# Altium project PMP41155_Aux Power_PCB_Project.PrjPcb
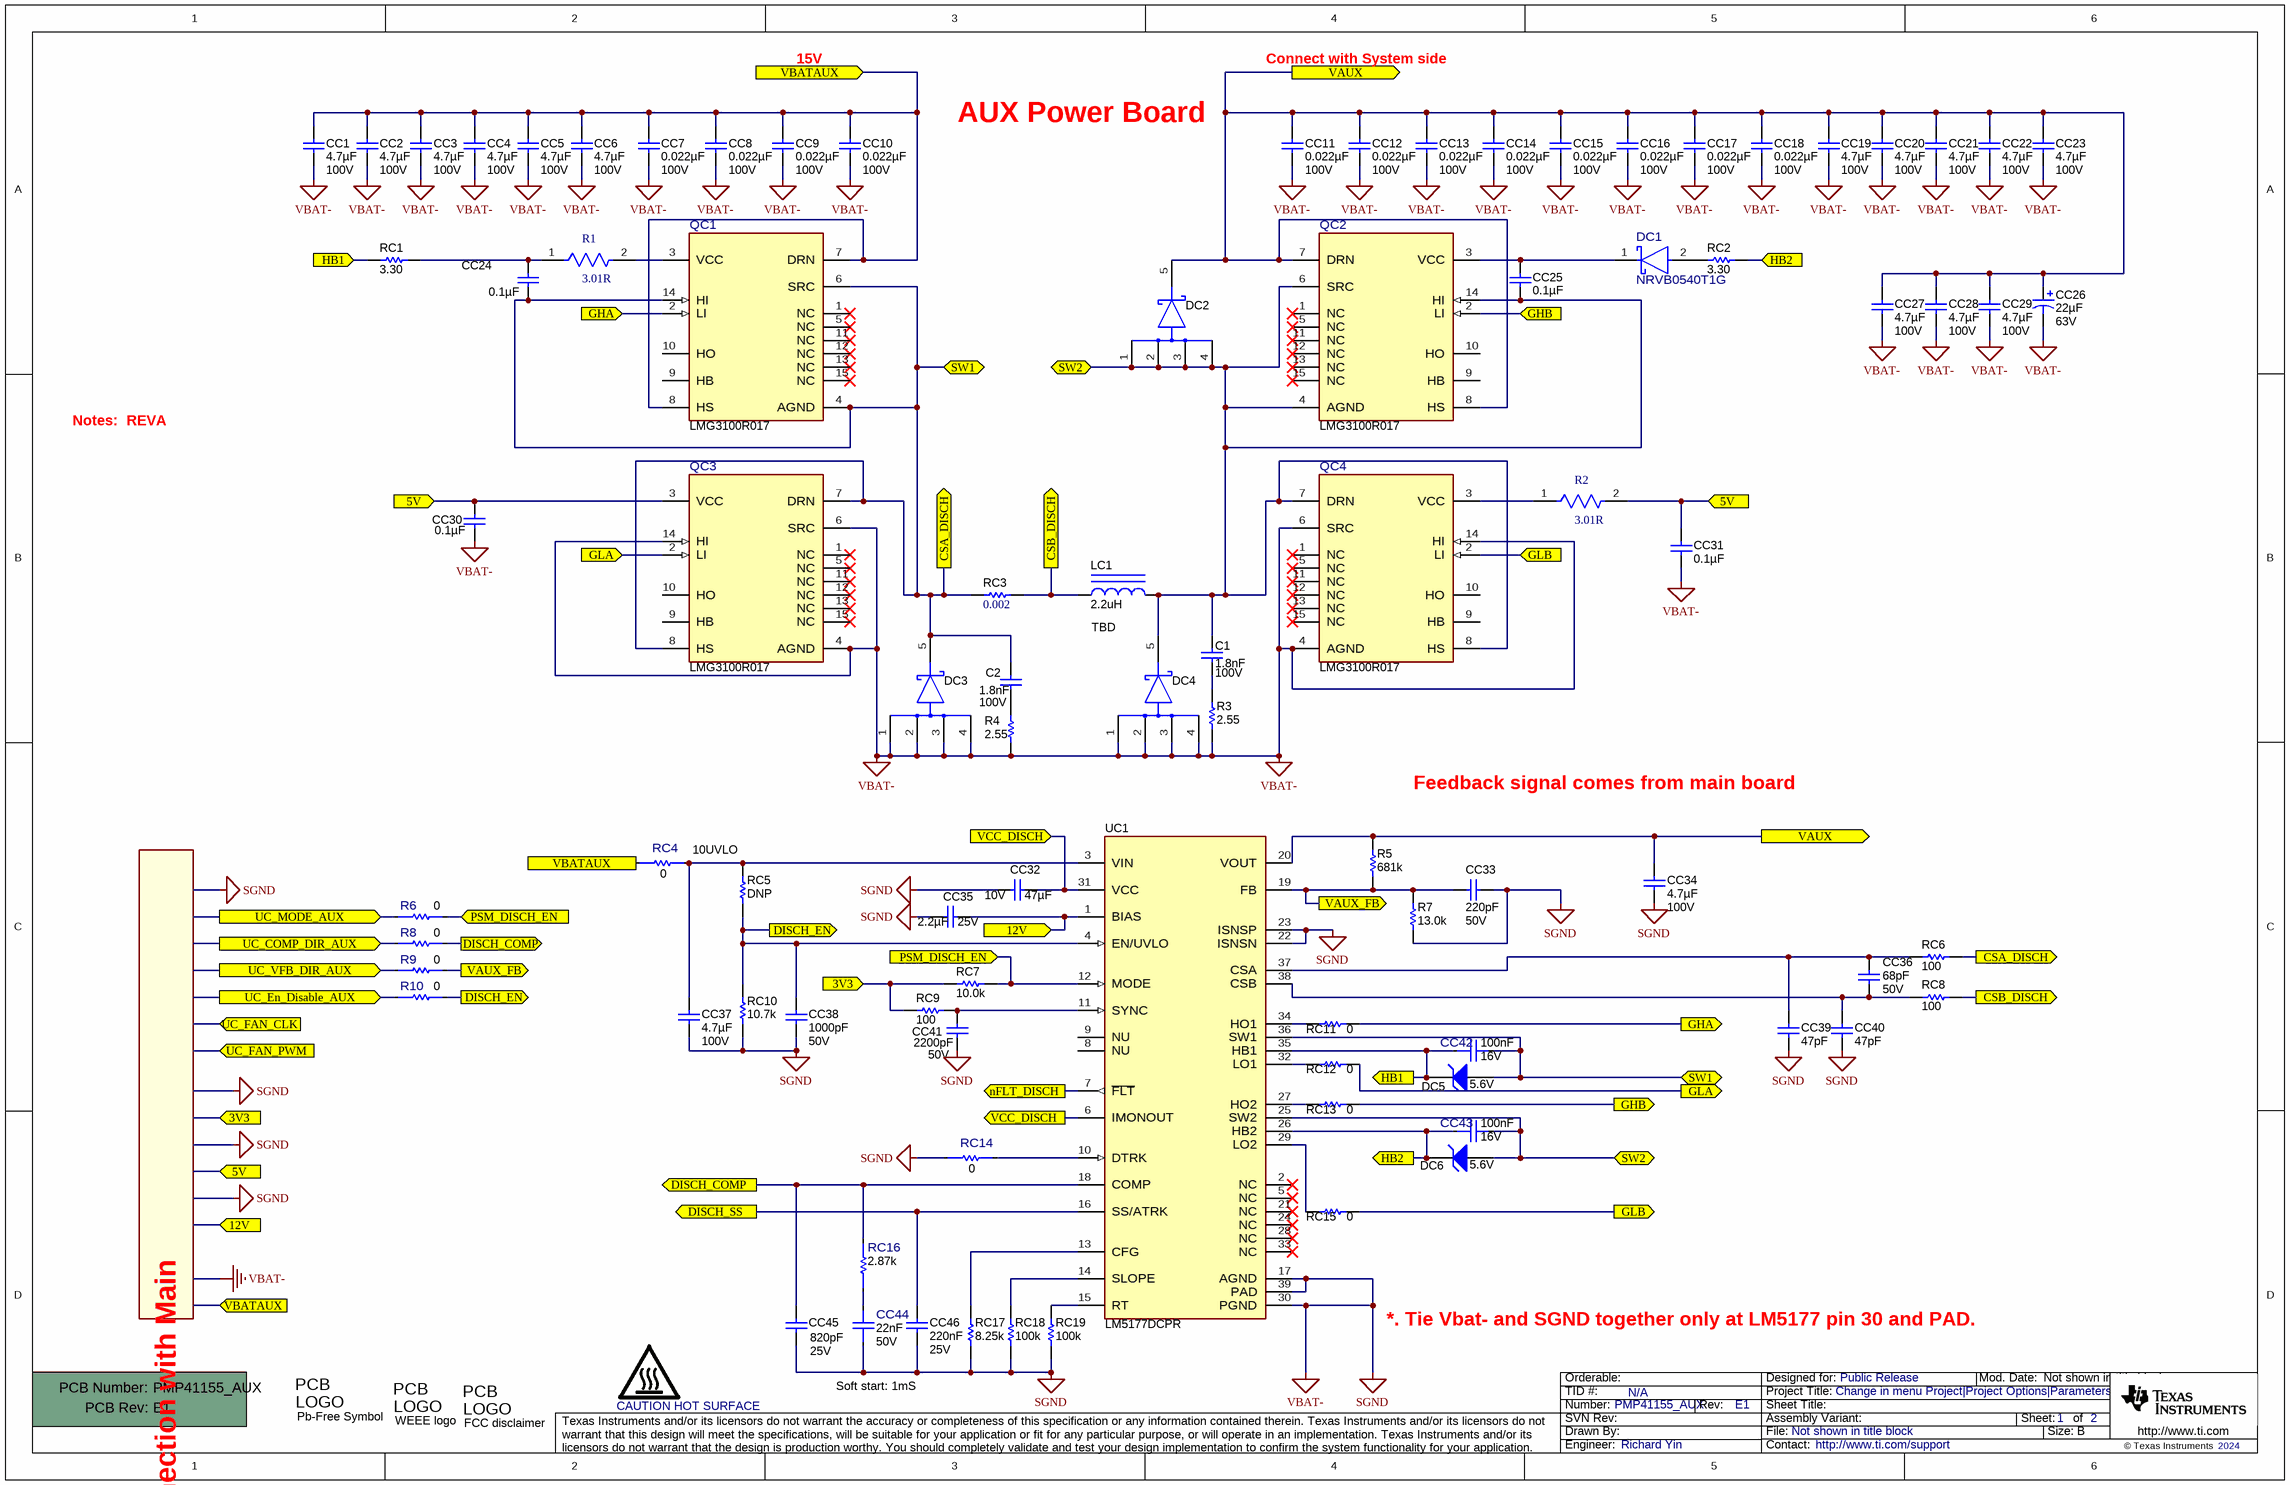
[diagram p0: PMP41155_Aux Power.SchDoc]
CopyrightYear: 2024; PCB_Layout: Richard Yin; PCB_Rev: E1; PRJ_Customer: Public Release; PRJ_Engineer: Richard Yin; PRJ_Number: PMP41155_AUX; PRJ_Title: Change in menu Project|Project Options|Parameters; SCH_Rev: E1; TechSupport: http://www.ti.com/support; TID: N/A
2 sheets, 131 parts. Net scope: flat (ports and power ports of the same name join across sheets).
Board file: PMP41155_Aux Power.PcbDoc
Sheets:
  PMP41155_Aux Power.SchDoc
  PMP41155_Aux Power_D2D.SchDoc

## Sheet PMP41155_Aux Power.SchDoc
size 431 x 279 mm; Date: Not shown in title block; ApprovedBy: Not shown in title block; CheckedBy: Not shown in title block; Author: Not shown in title block; CompanyName: Not shown in title block; Engineer: Not shown in title block; Organization: Not shown in title block; Address1: Not shown in title block; Address2: Not shown in title block; Address3: Not shown in title block; Address4: Not shown in title block; DocumentNumber: 1; Revision: Use project parameter SCH_Rev; SheetNumber: 1; SheetTotal: 2; PageSetup: Record=PageOptions¦CenterHorizontal=True¦CenterVertical=True¦PrintScale=1.00¦XCorrection=1.00¦YCorrection=1.00¦PrintKind=0¦BorderSize=5000000¦LeftOffset=0¦BottomOffset=0¦Orientation=2¦PaperLength=1000¦PaperWidth=1000¦Scale=100¦PaperSource=15¦PrintQuality=600¦MediaType=1¦DitherType=10¦PaperKind=Letter¦PrintScaleMode=1

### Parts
!PCB1  Printed Circuit Board  (value not drawn)  (mechanical)
C1  Cap_F: 1.8nF  VDC_V: 100V  [0603]  (hidden comment: GRM188R72A182KA01D)
C2  Cap_F: 1.8nF  VDC_V: 100V  [0603]  (hidden comment: GRM188R72A182KA01D)
CC1  ValueDisplayed: 4.7µF  Value2: 100V  [1206_180]  (hidden comment: GRJ31CC72A475KE01L)
CC2  ValueDisplayed: 4.7µF  Value2: 100V  [1206_180]  (hidden comment: GRJ31CC72A475KE01L)
CC3  ValueDisplayed: 4.7µF  Value2: 100V  [1206_180]  (hidden comment: GRJ31CC72A475KE01L)
CC4  ValueDisplayed: 4.7µF  Value2: 100V  [1206_180]  (hidden comment: GRJ31CC72A475KE01L)
CC5  ValueDisplayed: 4.7µF  Value2: 100V  [1206_180]  (hidden comment: GRJ31CC72A475KE01L)
CC6  ValueDisplayed: 4.7µF  Value2: 100V  [1206_180]  (hidden comment: GRJ31CC72A475KE01L)
CC7  ValueDisplayed: 0.022µF  Value2: 100V  [0603]  (hidden comment: CGA3E2X7R2A223K080AA)
CC8  ValueDisplayed: 0.022µF  Value2: 100V  [0603]  (hidden comment: CGA3E2X7R2A223K080AA)
CC9  ValueDisplayed: 0.022µF  Value2: 100V  [0603]  (hidden comment: CGA3E2X7R2A223K080AA)
CC10  ValueDisplayed: 0.022µF  Value2: 100V  [0603]  (hidden comment: CGA3E2X7R2A223K080AA)
CC11  ValueDisplayed: 0.022µF  Value2: 100V  [0603]  (hidden comment: CGA3E2X7R2A223K080AA)
CC12  ValueDisplayed: 0.022µF  Value2: 100V  [0603]  (hidden comment: CGA3E2X7R2A223K080AA)
CC13  ValueDisplayed: 0.022µF  Value2: 100V  [0603]  (hidden comment: CGA3E2X7R2A223K080AA)
CC14  ValueDisplayed: 0.022µF  Value2: 100V  [0603]  (hidden comment: CGA3E2X7R2A223K080AA)
CC15  ValueDisplayed: 0.022µF  Value2: 100V  [0603]  (hidden comment: CGA3E2X7R2A223K080AA)
CC16  ValueDisplayed: 0.022µF  Value2: 100V  [0603]  (hidden comment: CGA3E2X7R2A223K080AA)
CC17  ValueDisplayed: 0.022µF  Value2: 100V  [0603]  (hidden comment: CGA3E2X7R2A223K080AA)
CC18  ValueDisplayed: 0.022µF  Value2: 100V  [0603]  (hidden comment: CGA3E2X7R2A223K080AA)
CC19  ValueDisplayed: 4.7µF  Value2: 100V  [1206_180]  (hidden comment: GRJ31CC72A475KE01L)
CC20  ValueDisplayed: 4.7µF  Value2: 100V  [1206_180]  (hidden comment: GRJ31CC72A475KE01L)
CC21  ValueDisplayed: 4.7µF  Value2: 100V  [1206_180]  (hidden comment: GRJ31CC72A475KE01L)
CC22  ValueDisplayed: 4.7µF  Value2: 100V  [1206_180]  (hidden comment: GRJ31CC72A475KE01L)
CC23  ValueDisplayed: 4.7µF  Value2: 100V  [1206_180]  (hidden comment: GRJ31CC72A475KE01L)
CC24  ValueDisplayed: 0.1µF  [0402]  (hidden comment: C0402C104K4RACAUTO)
CC25  ValueDisplayed: 0.1µF  [0402]  (hidden comment: C0402C104K4RACAUTO)
CC26  ValueDisplayed: 22µF  Value2: 63V  [SM_RADIAL_D]  (hidden comment: 63PFV22M6.3X8)
CC27  ValueDisplayed: 4.7µF  Value2: 100V  [1206_180]  (hidden comment: GRJ31CC72A475KE01L)
CC28  ValueDisplayed: 4.7µF  Value2: 100V  [1206_180]  (hidden comment: GRJ31CC72A475KE01L)
CC29  ValueDisplayed: 4.7µF  Value2: 100V  [1206_180]  (hidden comment: GRJ31CC72A475KE01L)
CC30  ValueDisplayed: 0.1µF  [0402]  (hidden comment: C0402C104K4RACAUTO)
CC31  ValueDisplayed: 0.1µF  [0402]  (hidden comment: C0402C104K4RACAUTO)
CC32  VDC_V: 10V  ValueDisplayed: 47µF  [0805_HV]  (hidden comment: GRM21BR61A476ME15L)
CC33  ValueDisplayed: 220pF  Value2: 50V  [0603]  (hidden comment: GRM188R71H221KA01D)
CC34  ValueDisplayed: 4.7µF  Value2: 100V  [1206_180]  (hidden comment: GRJ31CC72A475KE01L)
CC35  ValueDisplayed: 2.2µF  Value2: 25V  [0805_HV]  (hidden comment: GRM219R61E225KA12D)
CC36  ValueDisplayed: 68pF  Value2: 50V  [0603]  (hidden comment: 06035A680JAT2A)
CC37  ValueDisplayed: 4.7µF  Value2: 100V  [1206_180]  (hidden comment: GRJ31CC72A475KE01L)
CC38  ValueDisplayed: 1000pF  Value2: 50V  [0603]  (hidden comment: GRM1885C1H102JA01D)
CC39  ValueDisplayed: 47pF  [0402]  (hidden comment: GRM1555C1H470FA01D)
CC40  ValueDisplayed: 47pF  [0402]  (hidden comment: GRM1555C1H470FA01D)
CC41  ValueDisplayed: 2200pF  Value2: 50V  [0603]  (hidden comment: GRM188R61H222KA01D)
CC42  Cap_F: 100nF  VDC_V: 16V  [FP-0603YC104JAT2A_0603-MFG]  (hidden comment: 0603YC104JAT2A)
CC43  Cap_F: 100nF  VDC_V: 16V  [FP-0603YC104JAT2A_0603-MFG]  (hidden comment: 0603YC104JAT2A)
CC44  Cap_F: 22nF  VDC_V: 50V  [FP-CL10B223KB8NNNC_0603-IPC_C]  (hidden comment: CL10B223KB8NNNC)
CC45  VDC_V: 25V  ValueDisplayed: 820pF  [0603]  (hidden comment: GRM1885C1E821JA01D)
CC46  Cap_F: 220nF  VDC_V: 25V  [0805_HV]  (hidden comment: 08053C224MAT2A)
DC1  NRVB0540T1G  [FP-NRVB0540T1G_SOD-123-MFG]
DC2  STPS30M100DJF-TR  [FP-STPS30M100DJF-TR_PowerFlat6-MFG]  (value not drawn)
DC3  STPS30M100DJF-TR  [FP-STPS30M100DJF-TR_PowerFlat6-MFG]  (value not drawn)
DC4  STPS30M100DJF-TR  [FP-STPS30M100DJF-TR_PowerFlat6-MFG]  (value not drawn)
DC5  value 5.6V  [SOD-123]  (hidden comment: MMSZ4690-E3-08)
DC6  value 5.6V  [SOD-123]  (hidden comment: MMSZ4690-E3-08)
LC1  TBD  ValueDisplayed: 2.2uH  [WE-HCB_1890]
LOGO1  CAUTION HOT SURFACE  [IEC_HotSurface_Small]  (no BOM)
Logo2  Pb-Free Symbol  [Pb-Free_Overlay_Medium]  (no BOM)
Logo3  WEEE logo  [WEEE_Minimum]  (no BOM)
Logo4  FCC disclaimer  [FCC_disclaimer]  (no BOM)
QC1  LMG3100R017  [VBE0015A-MFG]
QC2  LMG3100R017  [VBE0015A-MFG]
QC3  LMG3100R017  [VBE0015A-MFG]
QC4  LMG3100R017  [VBE0015A-MFG]
R1  Resistance: 3.01R  [FP-CRCW0402-e3-MFG]  (hidden comment: CRCW04023R01FNED)
R2  Resistance: 3.01R  [FP-CRCW0402-e3-MFG]  (hidden comment: CRCW04023R01FNED)
R3  ValueDisplayed: 2.55  [1206]  (hidden comment: CRCW12062R55FKEA)
R4  ValueDisplayed: 2.55  [1206]  (hidden comment: CRCW12062R55FKEA)
R5  ValueDisplayed: 681k  [0603]  (hidden comment: CRCW0603681KFKEA)
R6  Res_ohm: 0  [FP-D1LPC0402CJUMPF-T10_0402-MFG]  (hidden comment: D1LPC0402CJUMPF-T10)
R7  ValueDisplayed: 13.0k  [0603]  (hidden comment: CRCW060313K0FKEA)
R8  Res_ohm: 0  [FP-D1LPC0402CJUMPF-T10_0402-MFG]  (hidden comment: D1LPC0402CJUMPF-T10)
R9  Res_ohm: 0  [FP-D1LPC0402CJUMPF-T10_0402-MFG]  (hidden comment: D1LPC0402CJUMPF-T10)
R10  Res_ohm: 0  [FP-D1LPC0402CJUMPF-T10_0402-MFG]  (hidden comment: D1LPC0402CJUMPF-T10)
RC1  ValueDisplayed: 3.30  [1206]  (hidden comment: RC1206FR-073R3L)
RC2  ValueDisplayed: 3.30  [1206]  (hidden comment: RC1206FR-073R3L)
RC3  ValueDisplayed: 0.002  [0508]  (hidden comment: KRL2012E-M-R002-G-T5)
RC4  Res_ohm: 0  [FP-JR0805X35E_0805-MFG]  (hidden comment: JR0805X35E)
RC5  ValueDisplayed: DNP  [0402]  (hidden comment: CRCW040271K5FKED)
RC6  ValueDisplayed: 100  [0603]  (hidden comment: RC0603FR-07100RL)
RC7  ValueDisplayed: 10.0k  [0603]  (hidden comment: CRCW060310K0FKEA)
RC8  ValueDisplayed: 100  [0603]  (hidden comment: RC0603FR-07100RL)
RC9  ValueDisplayed: 100  [0603]  (hidden comment: CRCW0603100RFKEA)
RC10  ValueDisplayed: 10.7k  [0603]  (hidden comment: CRCW060310K7FKEA)
RC11  ValueDisplayed: 0  [0603]  (hidden comment: CRCW06030000Z0EA)
RC12  ValueDisplayed: 0  [0603]  (hidden comment: CRCW06030000Z0EA)
RC13  ValueDisplayed: 0  [0603]  (hidden comment: CRCW06030000Z0EA)
RC14  Res_ohm: 0  [FP-JR0805X35E_0805-MFG]  (hidden comment: JR0805X35E)
RC15  ValueDisplayed: 0  [0603]  (hidden comment: CRCW06030000Z0EA)
RC16  Res_ohm: 2.87k  [FP-RK73H1ETTP2871F_0402-MFG]  (hidden comment: RK73H1ETTP2871F)
RC17  ValueDisplayed: 8.25k  [0603]  (hidden comment: CRCW06038K25FKEA)
RC18  ValueDisplayed: 100k  [0603]  (hidden comment: CRCW0603100KFKEA)
RC19  ValueDisplayed: 100k  [0603]  (hidden comment: CRCW0603100KFKEA)
UC1  LM5177DCPR  [DCP0038A-MFG]

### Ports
3V3 (in), 5V (in), 12V (in), CSA_DISCH (out), CSB_DISCH (out), DISCH_COMP (out), DISCH_EN (out), DISCH_SS (out), GHA (in), GHA (out), GHB (in), GHB (out), GLA (in), GLA (out), GLB (in), GLB (out), HB1 (in), HB1 (out), HB2 (in), HB2 (out), nFLT_DISCH (out), PSM_DISCH_EN (in), SW1 (bidir), SW2 (bidir), UC_COMP_DIR_AUX (out), UC_En_Disable_AUX (out), UC_FAN_CLK (in), UC_FAN_PWM (in), UC_MODE_AUX (out), UC_VFB_DIR_AUX (out), VAUX (out), VAUX_FB (out), VBATAUX (in), VCC_DISCH (in), VCC_DISCH (out)

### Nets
12V: CC35.2 UC1.1(BIAS) ; port 12V
SGND: CC1.2 CC2.2 CC3.2 CC4.2 CC5.2 CC6.2 CC7.2 CC8.2 CC9.2 CC10.2 CC11.2 CC12.2 CC13.2 CC14.2 CC15.2 CC16.2 CC17.2 CC18.2 CC19.2 CC20.2 CC21.2 CC22.2 CC23.2 CC26.2(-) CC27.2 CC28.2 CC29.2 CC30.2 CC31.2 CC32.2 CC33.2 CC34.2 CC35.1 CC37.2 CC38.2 CC39.2 CC40.2 CC41.1 CC44.1 CC45.2 CC46.2 DC3.1(A) DC3.2(A) DC3.3(A) DC3.4(A) DC4.1(A) DC4.2(A) DC4.3(A) DC4.4(A) QC3.4(AGND) QC3.6(SRC) QC3.14(HI) QC4.4(AGND) QC4.6(SRC) QC4.14(HI) R3.1 R4.1 R7.1 RC10.1 RC14.1 RC17.1 RC18.1 RC19.1 UC1.17(AGND) UC1.22(ISNSN) UC1.23(ISNSP) UC1.30(PGND) UC1.39(PAD)  [also labelled VBAT-]
VAUX: CC11.1 CC12.1 CC13.1 CC14.1 CC15.1 CC16.1 CC17.1 CC18.1 CC19.1 CC20.1 CC21.1 CC22.1 CC23.1 CC26.1(+) CC27.1 CC28.1 CC29.1 CC34.1 DC2.5(K) QC2.7(DRN) QC2.8(HS) R5.2 UC1.20(VOUT) ; port VAUX
3V3: RC7.1 RC9.1 ; port 3V3
5V: CC30.1 CC31.1 QC3.3(VCC) R2.2 ; port 5V
CSA_DISCH: C2.1 CC24.2 CC42.2 DC3.5(K) DC5.2(A) QC1.4(AGND) QC1.6(SRC) QC1.14(HI) QC3.7(DRN) QC3.8(HS) RC3.1 RC6.2 UC1.36(SW1) ; port CSA_DISCH, port SW1
CSB_DISCH: LC1.1 RC3.2 RC8.2 ; port CSB_DISCH
DISCH_COMP: CC45.1 R8.2 RC16.2 UC1.18(COMP) ; port DISCH_COMP
DISCH_EN: CC38.1 R10.2 RC5.1 RC10.2 UC1.4(EN/UVLO) ; port DISCH_EN
DISCH_SS: CC46.1 UC1.16(SS/ATRK) ; port DISCH_SS
GHA: QC1.2(LI) RC11.2 ; port GHA
GHB: QC2.2(LI) RC13.2 ; port GHB
GLA: QC3.2(LI) RC12.2 ; port GLA
GLB: QC4.2(LI) RC15.2 ; port GLB
HB1: CC42.1 DC5.1(K) RC1.1 UC1.35(HB1) ; port HB1
HB2: CC43.1 DC6.1(K) RC2.2 UC1.26(HB2) ; port HB2
nFLT_DISCH: UC1.7(~{FLT}) ; port nFLT_DISCH
PSM_DISCH_EN: R6.2 RC7.2 UC1.12(MODE) ; port PSM_DISCH_EN
SW2: C1.1 CC25.2 CC43.2 DC2.1(A) DC2.2(A) DC2.3(A) DC2.4(A) DC4.5(K) DC6.2(A) LC1.2 QC2.4(AGND) QC2.6(SRC) QC2.14(HI) QC4.7(DRN) QC4.8(HS) UC1.25(SW2) ; port SW2
UC_COMP_DIR_AUX: R8.1 ; port UC_COMP_DIR_AUX
UC_En_Disable_AUX: R10.1 ; port UC_En_Disable_AUX
UC_MODE_AUX: R6.1 ; port UC_MODE_AUX
UC_VFB_DIR_AUX: R9.1 ; port UC_VFB_DIR_AUX
VAUX_FB: CC33.1 R5.1 R7.2 R9.2 UC1.19(FB) ; port VAUX_FB
VBATAUX: CC1.1 CC2.1 CC3.1 CC4.1 CC5.1 CC6.1 CC7.1 CC8.1 CC9.1 CC10.1 QC1.7(DRN) QC1.8(HS) RC4.1 ; port VBATAUX
VCC_DISCH: CC32.1 UC1.6(IMONOUT) UC1.31(VCC) ; port VCC_DISCH
NetC1_2: C1.2 R3.2
NetC2_2: C2.2 R4.2
NetCC24_1: CC24.1 R1.1 RC1.2
NetCC25_1: CC25.1 DC1.1(CATHODE) QC2.3(VCC)
NetCC36_1: CC36.1 CC39.1 RC6.1 UC1.37(CSA)
NetCC36_2: CC36.2 CC40.1 RC8.1 UC1.38(CSB)
NetCC37_1: CC37.1 RC4.2 RC5.2 UC1.3(VIN)
NetCC41_2: CC41.2 RC9.2 UC1.11(SYNC)
NetCC44_2: CC44.2 RC16.1
NetDC1_2: DC1.2(ANODE) RC2.1
NetQC1_3: QC1.3(VCC) R1.2
NetQC4_3: QC4.3(VCC) R2.1
NetRC11_1: RC11.1 UC1.34(HO1)
NetRC12_1: RC12.1 UC1.32(LO1)
NetRC13_1: RC13.1 UC1.27(HO2)
NetRC14_2: RC14.2 UC1.10(DTRK)
NetRC15_1: RC15.1 UC1.29(LO2)
NetRC17_2: RC17.2 UC1.13(CFG)
NetRC18_2: RC18.2 UC1.14(SLOPE)
NetRC19_2: RC19.2 UC1.15(RT)

Not connected (* = marked no-connect by the designer): QC1 1(NC)* 5(NC)* 9(HB) 10(HO) 11(NC)* 12(NC)* 13(NC)* 15(NC)*; QC2 1(NC)* 5(NC)* 9(HB) 10(HO) 11(NC)* 12(NC)* 13(NC)* 15(NC)*; QC3 1(NC)* 5(NC)* 9(HB) 10(HO) 11(NC)* 12(NC)* 13(NC)* 15(NC)*; QC4 1(NC)* 5(NC)* 9(HB) 10(HO) 11(NC)* 12(NC)* 13(NC)* 15(NC)*; UC1 2(NC)* 5(NC)* 8(NU) 9(NU) 21(NC)* 24(NC)* 28(NC)* 33(NC)*

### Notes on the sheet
- 15V
- Connect with System side
- AUX Power Board
- Notes:
- REVA
- Feedback signal comes from main board
- 10UVLO
- Connection with Main
- *. Tie Vbat- and SGND together only at LM5177 pin 30 and PAD.
- Soft start: 1mS

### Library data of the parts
!PCB1 = CMP-0003618-2: Manufacturer: Any; PartNumber: PMP41155_AUX
C1 C2 = CMP-0007473-4: CAP, CERM, 1800 pF, 100 V, +/- 10%, X7R, 0603; Manufacturer: MuRata; TaMin_C: -55°C; Polarized: N; SizeAreaWB_mm2: 4.68; Value1: Unknown; U/M: EA; Value: 1800pF; TaMax_C: 125°C; SizeZ_mm: 1; SizeX_mm: 1.6; SizeY_mm: 0.8; SizeArea_mm2: 1.28; AEC Category: Q200
CC1-CC6 CC19-CC23 CC27-CC29 CC34 CC37 = C3216X6S1H475K160AB: CAP CER 4.7UF 100V X7S 1206; Polarized: N; CompType: Capacitor; U/M: EA; Cap_F: 0.0000047; Tolerance_%: 10; VDC_V: 100; TaMin_C: -55; TaMax_C: 105; Cap_Case: 1206; SizeArea_mm2: 5.12; SizeAreaWB_mm2: 10.92; SizeX_mm: 3.2; SizeY_mm: 1.6; SizeZ_mm: 1.8; AEC Category: Q200
CC7-CC18 = CGA3E2X7R2A223K080AA: CAP, CERM, 0.022 µF, 100 V,+/- 10%, X7R, AEC-Q200 Grade 1, 0603; Manufacturer: TDK; Polarized: N; CompType: Capacitor; Value: 0.022uF; U/M: EA; Cap_F: 0.000000022; Tolerance_%: 10; ESR_ohm: 0.083542; Value1: 0.083542 ohm; VDC_V: 100; IRMS_A: 0.609312; TaMin_C: -55; TaMax_C: 125; SizeArea_mm2: 1.28; SizeAreaWB_mm2: 4.68; SizeX_mm: 1.6; SizeY_mm: 0.8; SizeZ_mm: 1; AEC Category: Q200; AEC Qualified: Y
CC24 CC25 CC30 CC31 = C0402C104K4RACAUTO: CAP, CERM, 0.1 µF, 16 V,+/- 10%, X7R, AEC-Q200 Grade 1, 0402; Manufacturer: Kemet; Polarized: N; CompType: Capacitor; Value: 0.1uF; U/M: EA; Cap_F: 0.0000001; Tolerance_%: 10; VDC_V: 16; Value2: 16V; TaMin_C: -55; TaMax_C: 125; SizeArea_mm2: 0.5; SizeAreaWB_mm2: 3; SizeX_mm: 1; SizeZ_mm: 0.6; AEC Category: Q200; AEC Qualified: Y; Green_Lifecycle: Active; Green_REACh: Passed
CC26 = EEE-FK1H220P: CAP ALUM POLY HYB 22UF 63V SMD; Manufacturer: Rubycon; Polarized: Y; CompType: Capacitor; Cap_F: 0.000022; Tolerance_%: 20; Value1: 0.88 ohm; VDC_V: 63; Cap_Case: D; SizeAreaWB_mm2: 84.28; SizeArea_mm2: 51.48; SizeX_mm: 7.8; SizeY_mm: 6.6; SizeZ_mm: 5.4; Green_Lifecycle: Active; Green_REACh: Passed
CC32 = CMP-0078699-1: CAP, CERM, 47 µF, 10 V,+/- 20%, X5R, 0805; Manufacturer: MuRata; TaMin_C: -55°C; Polarized: N; Green_Lifecycle: Active; SizeAreaWB_mm2: 6.75; Green_REACh: Passed; U/M: EA; Value: 47uF; TaMax_C: 85°C; SizeZ_mm: 1.45; SizeX_mm: 2; SizeY_mm: 1.25; Cap_Case: 0805; SizeArea_mm2: 2.5; AEC Category: Q200
CC33 = GRM188R71H221KA01D: CAP, CERM, 220 pF, 50 V,+/- 10%, X7R, 0603; Manufacturer: MuRata; Polarized: N; CompType: Capacitor; Value: 220pF; U/M: EA; Cap_F: 0.00000000022; Tolerance_%: 10; VDC_V: 50; TaMin_C: -55; TaMax_C: 125; SizeArea_mm2: 1.28; SizeAreaWB_mm2: 4.68; SizeX_mm: 1.6; SizeY_mm: 0.8; SizeZ_mm: 1; AEC Category: Q200; Green_Lifecycle: Active; Green_REACh: Passed
CC35 = GRM219R61E225KA12D: CAP, CERM, 2.2 µF, 25 V,+/- 10%, X5R, 0805; Manufacturer: MuRata; Polarized: N; CompType: Capacitor; Value: 2.2uF; U/M: EA; Cap_F: 0.0000022; Tolerance_%: 10; ESR_ohm: 0.006; Value1: 0.006 ohm; VDC_V: 25; TaMin_C: -55; TaMax_C: 85; Cap_Case: 0805; SizeArea_mm2: 2.5; SizeAreaWB_mm2: 6.75; SizeX_mm: 2; SizeY_mm: 1.25; SizeZ_mm: 1.45; AEC Category: Q200; Green_Lifecycle: Active; Green_REACh: Passed
CC36 = 06035A680JAT2A: CAP, CERM, 68 pF, 50 V,+/- 5%, C0G/NP0, 0603; Manufacturer: AVX; Polarized: N; CompType: Capacitor; Value: 68pF; U/M: EA; Cap_F: 0.000000000068; Tolerance_%: 5; ESR_ohm: 0.144; Value1: 0.144 ohm; VDC_V: 50; TaMin_C: -55; TaMax_C: 125; SizeArea_mm2: 1.28; SizeAreaWB_mm2: 4.68; SizeX_mm: 1.6; SizeY_mm: 0.8; SizeZ_mm: 1; AEC Category: Q200; Green_Lifecycle: Active; Green_REACh: Passed
CC38 = GRM1885C1H102JA01D: CAP, CERM, 1000 pF, 50 V,+/- 5%, C0G/NP0, 0603; Manufacturer: MuRata; Polarized: N; CompType: Capacitor; Value: 1000pF; U/M: EA; Cap_F: 0.000000001; Tolerance_%: 5; VDC_V: 50; TaMin_C: -55; TaMax_C: 125; SizeArea_mm2: 1.28; SizeAreaWB_mm2: 4.68; SizeX_mm: 1.6; SizeY_mm: 0.8; SizeZ_mm: 1; AEC Category: Q200; Green_Lifecycle: Active; Green_REACh: Passed
CC39 CC40 = GRM1555C1H470FA01D: CAP, CERM, 47 pF, 50 V,+/- 1%, C0G/NP0, 0402; Manufacturer: MuRata; Polarized: N; CompType: Capacitor; Value: 47pF; U/M: EA; Cap_F: 0.000000000047; Tolerance_%: 1; VDC_V: 50; Value2: 50V; TaMin_C: -55; TaMax_C: 125; SizeArea_mm2: 0.5; SizeAreaWB_mm2: 3; SizeZ_mm: 0.6; AEC Category: Q200; Green_Lifecycle: Active; Green_REACh: Passed
CC41 = GRM188R61H222KA01D: CAP, CERM, 2200 pF, 50 V,+/- 10%, X5R, 0603; Manufacturer: MuRata; Polarized: N; CompType: Capacitor; Value: 2200pF; U/M: EA; Cap_F: 0.0000000022; Tolerance_%: 10; VDC_V: 50; TaMin_C: -55; TaMax_C: 85; SizeArea_mm2: 1.28; SizeAreaWB_mm2: 4.68; SizeX_mm: 1.6; SizeY_mm: 0.8; SizeZ_mm: 1; AEC Category: Q200
CC42 CC43 = CMP-0120699-1: 0.1 µF ±5% 16V Ceramic Capacitor X7R 0603 (1608 Metric); Manufacturer: KYOCERA AVX; AEC Qualified: No; SizeZ_mm: 0.9mm; TempCo: 15%; Value: 100nF
CC44 = CMP-0095696-1: Cap Ceramic 22nF 50V X7R ±10% Pad SMD 0603 +125°C T/R; Manufacturer: Samsung; TempCo: 0.15; SizeZ_mm: 0.9mm; AEC Qualified: No
CC45 = CMP-0007168-4: CAP, CERM, 820 pF, 25 V, +/- 5%, C0G/NP0, 0603; Manufacturer: MuRata; TaMin_C: -55°C; Polarized: N; SizeAreaWB_mm2: 4.68; Value1: Unknown; U/M: EA; Value: 820pF; TaMax_C: 125°C; SizeZ_mm: 1; SizeX_mm: 1.6; SizeY_mm: 0.8; SizeArea_mm2: 1.28; AEC Category: Q200
CC46 = CMP-0007572-2: CAP, CERM, 0.22 uF, 25 V, +/- 20%, X7R, 0805; Manufacturer: AVX; TaMin_C: -55°C; ESR_ohm: 16m; Polarized: N; SizeAreaWB_mm2: 6.75; Value1: 0.016 ohm; U/M: EA; Value: 0.22uF; TaMax_C: 125°C; SizeZ_mm: 1.45; SizeX_mm: 2; SizeY_mm: 1.25; Cap_Case: 0805; SizeArea_mm2: 2.5; AEC Category: Q200
DC1 = CMP-0090564-1: Diode Schottky 40V 500mA Surface Mount SOD-123; Manufacturer: On Semiconductor; Max Surge Forward Current: 5.5A; Standoff Height: 0mm; Import Ts: 1521847448; AEC Grade: Grade 0; AEC Qualified: Yes; Peak Reverse Current: 20uA; SizeZ_mm: 1.35mm; TJmax_C: 150°C; Ciiva Ids: 822523; Forward Current: 0.5A
DC2-DC4 = CMP-0032275-1: Diode 100 V 30A Surface Mount PowerFlat™ (5x6); Manufacturer: STMicroelectronics; AEC Qualified: No; SizeZ_mm: 1.05mm; TJmax_C: 150°C; Vf_V: 100V; Max Surge Forward Current: 200A; Peak Reverse Current: 100uA; Standoff Height: 0mm
DC5 DC6 = CMP-0077600-3: Diode, Zener, 5.6 V, 500 mW, SOD-123; Manufacturer: Vishay-Semiconductor; RJA_CperW: 340; SizeArea_mm2: 6.545; SizeAreaWB_mm2: 13.095; Value1: 0.5W; SizeZ_mm: 1.35; AEC Category: Q101; AEC Qualified: N; SizeX_mm: 3.85; SizeY_mm: 1.7; Power_W: 500mW
LC1 = CMP-0064042-1: Green_Lifecycle: Active; SizeAreaWB_mm2: 410.06; DCR_ohm: 1.6m; Green_REACh: Passed; SizeZ_mm: 9.2; SizeX_mm: 18.3; SizeY_mm: 18.2; SizeArea_mm2: 333.06; CompType: Inductor; Ind_H: 2.2µH; AEC Category: Q200
LOGO1 = CMP-0074837-1: IEC 61010-1 Hot Surface Warning; Library Reference: IEC_HotSurface; SymbolCreator: a0412235
Logo2 = Pb-Free: SymbolCreator: a0412235
Logo3 = CMP-0074769-1
Logo4 = CMP-0074847-1: FCC_disclaimer; Library Reference: Logo
QC1-QC4 = CMP-0037654-1: 100-V, 64-A GaN with Integrated Driver; Manufacturer: Texas Instruments; SizeZ_mm: 0.85mm; AEC Qualified: No; Max Supply Voltage: 5.25V; Min Supply Voltage: 4.75V; Nominal Supply Current: 3mA; Number Of Drivers: 1; Propagation Delay: 55ns; Standoff Height: 0mm; TJmax_C: +125°C
R1 R2 = CMP-02407-004899-1: RES Thick Film, 3.01Ω, 1%, 0.063W, 200ppm/°C, 0402; Max Power Dissipation: 63mW; Voltage Rating (DC): 50V
R3 R4 = CMP-0016888-3: RES, 2.55, 1%, 0.25 W, AEC-Q200 Grade 0, 1206; Manufacturer: Vishay-Dale; Power_W: 250mW; TempCo: 100 ppm/C; Value_Code: 2R55; Value: 2.55; EIA_Code: E96; SizeX_mm: 3.2; SizeY_mm: 1.6; SizeZ_mm: 1.35; Value2: 0.25W; SizeArea_mm2: 5.12; AEC Qualified: Y; VDC_V: 200V; AEC Category: Q200; AEC Grade: 0
R5 = CMP-0022550-4: RES, 681 k, 1%, 0.1 W, AEC-Q200 Grade 0, 0603; Manufacturer: Vishay-Dale; Power_W: 100mW; TempCo: 100 ppm/C; Value: 681k; EIA_Code: E96; SizeX_mm: 1.6; SizeY_mm: 0.8; SizeZ_mm: 1; Value2: 0.1W; SizeArea_mm2: 1.28; AEC Qualified: Y; VDC_V: 75V; AEC Category: Q200; AEC Grade: 0
R6 R8-R10 = CMP-0031873-1: 0 Ohms Jumper Chip Resistor 0402 (1005 Metric) Anti-Sulfur, Current Sense, Flame Retardant Coating, Moisture Resistant, Safety Metal Foil; Manufacturer: Thin Film Technology; AEC Qualified: No; SizeZ_mm: 0.45mm; Max Current: 20A; Value: 0
R7 = CMP-0022042-4: RES, 13.0 k, 1%, 0.1 W, AEC-Q200 Grade 0, 0603; Manufacturer: Vishay-Dale; Power_W: 100mW; TempCo: 100 ppm/C; Value_Code: 13k0; Value: 13.0k; EIA_Code: E96; Res_ohm: 13k; SizeX_mm: 1.6; SizeY_mm: 0.8; SizeZ_mm: 1; Value2: 0.1W; SizeArea_mm2: 1.28; AEC Qualified: Y; VDC_V: 75V; AEC Category: Q200; AEC Grade: 0
RC1 RC2 = CMP-0018270-2: RES, 3.30, 1%, 0.25 W, 1206; Manufacturer: Yageo America; Power_W: 250mW; TempCo: 200 ppm/C; Value_Code: 3R30; U/M: EA; Value: 3.30; Res_ohm: 3.3; SizeX_mm: 3.2; SizeY_mm: 1.6; SizeZ_mm: 1.35; Value2: 0.25W; SizeArea_mm2: 5.12; VDC_V: 200V; AEC Category: Q200
RC3 = CMP-0015357-3: RES, 0.002, 2%, 1 W, 0508; Manufacturer: Susumu Co Ltd; Power_W: 1W; TempCo: 100 ppm/C; SizeAreaWB_mm2: 6.75; Value_Code: 2L000; U/M: EA; Value: 0.002; Res_ohm: 2m; SizeX_mm: 1.25; SizeY_mm: 2; SizeZ_mm: 1; SizeArea_mm2: 2.5; AEC Category: Q200
RC4 RC14 = CMP-0096818-1: 0 Ohms Jumper 0.245W Chip Resistor 0805 (2012 Metric) - Metal Element; Manufacturer: Ohmite; AEC Qualified: No; Value: 0; Power_W: 245mW; SizeZ_mm: 0.55mm
RC5 = CMP-0026535-2: RES, 71.5 k, 1%, 0.063 W, AEC-Q200 Grade 0, 0402; Manufacturer: Vishay-Dale; Power_W: 63mW; TempCo: 100 ppm/C; Value_Code: 71k5; Value: 71.5k; EIA_Code: E96; SizeX_mm: 1; SizeY_mm: 0.5; SizeZ_mm: 0.6; Value2: 0.063W; AEC Qualified: Y; VDC_V: 50V; AEC Category: Q200; AEC Grade: 0
RC6 RC8 = RC0603FR-07100RL: RES, 100, 1%, 0.1 W, 0603; Manufacturer: Yageo America; CompType: Resistor; Value: 100; Value_Code: 100R; Tolerance_%: 1; Power_W: 0.1; Value2: 0.1W; VDC_V: 150; TempCo: 200 ppm/C; SizeArea_mm2: 1.28; SizeX_mm: 1.6; SizeY_mm: 0.8; EIA_Code: E96; U/M: EA; AEC Category: Q200; Green_Lifecycle: Active; Green_REACh: Passed
RC7 = CRCW060310K0FKEA: RES, 10.0 k, 1%, 0.1 W, 0603; Manufacturer: Vishay-Dale; CompType: Resistor; Value: 10.0k; Res_ohm: 10000; Value_Code: 10k0; Tolerance_%: 1; Power_W: 0.1; Value2: 0.1W; VDC_V: 75; TempCo: 100 ppm/C; SizeArea_mm2: 1.28; SizeX_mm: 1.6; SizeY_mm: 0.8; EIA_Code: E96; U/M: EA; AEC Category: Q200; Green_Lifecycle: Active; Green_REACh: Passed
RC9 = CRCW0603100RFKEA: RES, 100, 1%, 0.1 W, 0603; Manufacturer: Vishay-Dale; CompType: Resistor; Value: 100; Value_Code: 100R; Tolerance_%: 1; Power_W: 0.1; Value2: 0.1W; VDC_V: 75; TempCo: 100 ppm/C; SizeArea_mm2: 1.28; SizeX_mm: 1.6; SizeY_mm: 0.8; EIA_Code: E96; U/M: EA; AEC Category: Q200; Green_Lifecycle: Active; Green_REACh: Passed
RC10 = CRCW060310K7FKEA: RES, 10.7 k, 1%, 0.1 W, 0603; Manufacturer: Vishay-Dale; CompType: Resistor; Value: 10.7k; Res_ohm: 10700; Value_Code: 10k7; Tolerance_%: 1; Power_W: 0.1; Value2: 0.1W; VDC_V: 75; TempCo: 100 ppm/C; SizeArea_mm2: 1.28; SizeX_mm: 1.6; SizeY_mm: 0.8; EIA_Code: E96; U/M: EA; AEC Category: Q200; Green_Lifecycle: Active; Green_REACh: Passed
RC11-RC13 RC15 = CMP-0025697-4: RES, 0, 5%, 0.1 W, AEC-Q200 Grade 0, 0603; Manufacturer: Vishay-Dale; Power_W: 100mW; TempCo: 200 ppm/C; Value_Code: 0000; Value: 0; EIA_Code: E24; SizeX_mm: 1.6; SizeY_mm: 0.8; SizeZ_mm: 1; Value2: 0.1W; SizeArea_mm2: 1.28; AEC Qualified: Y; VDC_V: 75V; AEC Category: Q200
RC16 = CMP-0089989-1: 2.87 kOhms ±1% 0.1W, 1/10W Chip Resistor 0402 (1005 Metric) Automotive AEC-Q200, Moisture Resistant Thick Film; Manufacturer: KOA Speer; AEC Qualified: Yes; VDC_V: 75V; Value: 2.87k; SizeZ_mm: 0.4mm; AEC Grade: Grade 0; TempCo: 100ppm/°C; Power_W: 100mW; Standoff Height: 0mm
RC17 = CRCW06038K25FKEA: RES, 8.25 k, 1%, 0.1 W, 0603; Manufacturer: Vishay-Dale; CompType: Resistor; Value: 8.25k; Res_ohm: 8250; Value_Code: 8k25; Tolerance_%: 1; Power_W: 0.1; Value2: 0.1W; VDC_V: 75; TempCo: 100 ppm/C; SizeArea_mm2: 1.28; SizeX_mm: 1.6; SizeY_mm: 0.8; EIA_Code: E96; U/M: EA; AEC Category: Q200; Green_Lifecycle: Active; Green_REACh: Passed
RC18 RC19 = CRCW0603100KFKEA: RES, 100 k, 1%, 0.1 W, 0603; Manufacturer: Vishay-Dale; CompType: Resistor; Value: 100k; Res_ohm: 100000; Tolerance_%: 1; Power_W: 0.1; Value2: 0.1W; VDC_V: 75; TempCo: 100 ppm/C; SizeArea_mm2: 1.28; SizeX_mm: 1.6; SizeY_mm: 0.8; EIA_Code: E96; U/M: EA; AEC Category: Q200; Green_Lifecycle: Active; Green_REACh: Passed
UC1 = CMP-0094661-2: Wide VIN Bidirectional 4 Switch Buck-Boost Controller; Manufacturer: Texas Instruments; Output Voltage: 3.3-78V; Max Supply Voltage: 78V; AEC Qualified: No; SizeZ_mm: 1.2mm; Switching Frequency: 100-2000kHz; AEC Category: Q200; Number Of Outputs: 2; Min Supply Voltage: 2.8V; Output Type: AdjustableProgrammable; Max Duty Cycle: 100%; CompType: IC; Standoff Height: 0.05mm; Nominal Supply Current: 25uA; TJmax_C: +125°C

## Sheet PMP41155_Aux Power_D2D.SchDoc
size 431 x 279 mm; Date: Not shown in title block; ApprovedBy: Not shown in title block; CheckedBy: Not shown in title block; Author: Not shown in title block; CompanyName: Not shown in title block; Engineer: Not shown in title block; Organization: Not shown in title block; Address1: Not shown in title block; Address2: Not shown in title block; Address3: Not shown in title block; Address4: Not shown in title block; DocumentNumber: 1; Revision: Use project parameter SCH_Rev; SheetNumber: 2; SheetTotal: 2; PageSetup: Record=PageOptions¦CenterHorizontal=True¦CenterVertical=True¦PrintScale=1.00¦XCorrection=1.00¦YCorrection=1.00¦PrintKind=0¦BorderSize=5000000¦LeftOffset=0¦BottomOffset=0¦Orientation=2¦PaperLength=1000¦PaperWidth=1000¦Scale=100¦PaperSource=15¦PrintQuality=600¦MediaType=1¦DitherType=10¦PaperKind=Letter¦PrintScaleMode=1
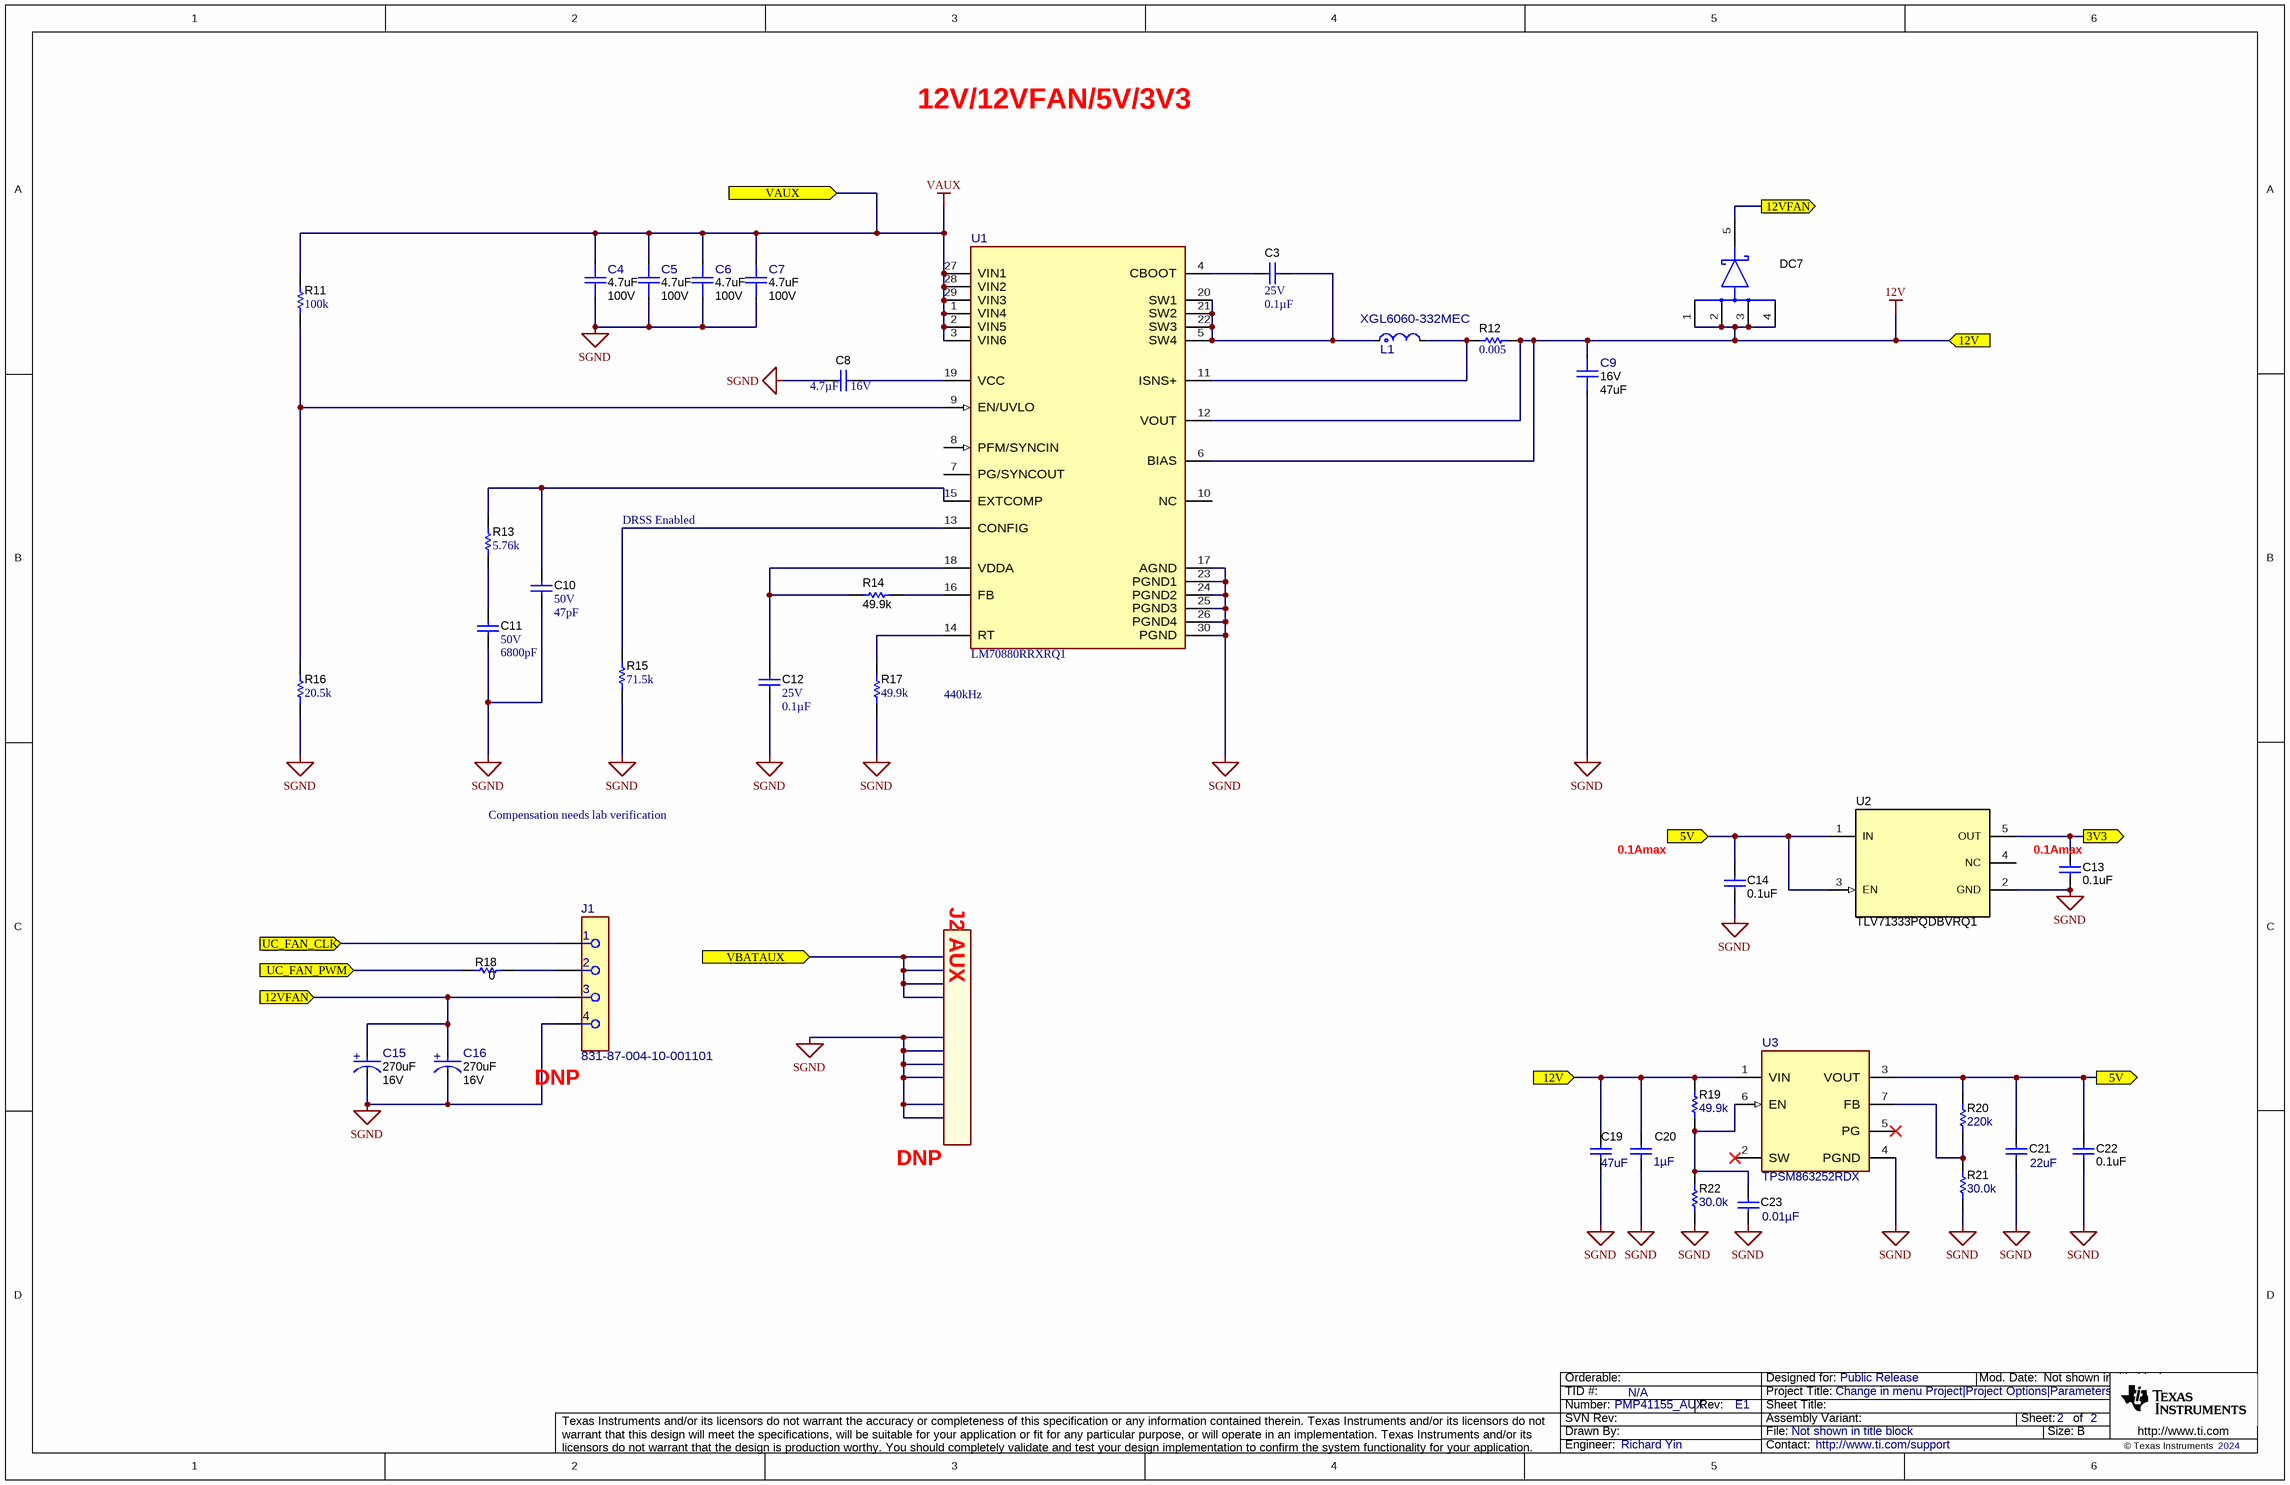
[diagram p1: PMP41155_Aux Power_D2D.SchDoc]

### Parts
C3  VDC_V: 25V  ValueDisplayed: 0.1µF  [0402]  (hidden comment: CGA2B3X7R1E104K050BB)
C4  ValueDisplayed: 4.7uF  VDC_V: 100V  [FP-CGA1206X7R475M101NT_1206-IPC_C]  (hidden comment: CGA1206X7R475M101NT)
C5  ValueDisplayed: 4.7uF  VDC_V: 100V  [FP-CGA1206X7R475M101NT_1206-IPC_C]  (hidden comment: CGA1206X7R475M101NT)
C6  ValueDisplayed: 4.7uF  VDC_V: 100V  [FP-CGA1206X7R475M101NT_1206-IPC_C]  (hidden comment: CGA1206X7R475M101NT)
C7  ValueDisplayed: 4.7uF  VDC_V: 100V  [FP-CGA1206X7R475M101NT_1206-IPC_C]  (hidden comment: CGA1206X7R475M101NT)
C8  Cap_F: 4.7µF  VDC_V: 16V  [0805_HV]  (hidden comment: CGA4J3X7R1C475K125AE)
C9  VDC_V: 16V  ValueDisplayed: 47uF  [FP-EMK325ABJ476KMHP_1210-MFG]  (hidden comment: EMK325ABJ476KMHP)
C10  VDC_V: 50V  ValueDisplayed: 47pF  [0402]  (hidden comment: CGA2B2NP01H470J050BA)
C11  VDC_V: 50V  ValueDisplayed: 6800pF  [0402]  (hidden comment: CGA2B2X7R1H682K050BA)
C12  VDC_V: 25V  ValueDisplayed: 0.1µF  [0402]  (hidden comment: CGA2B3X7R1E104K050BB)
C13  ValueDisplayed: 0.1uF  [0402]  (hidden comment: GRM152B30J104KE19)
C14  ValueDisplayed: 0.1uF  [0402]  (hidden comment: GRM152B30J104KE19)
C15  ValueDisplayed: 270uF  VDC_V: 16V  [FP-APXJ160ARA271MF80J_SMT_CAP_6MM6_6MM6-MFG]  (hidden comment: APXJ160ARA271MF80J)
C16  ValueDisplayed: 270uF  VDC_V: 16V  [FP-APXJ160ARA271MF80J_SMT_CAP_6MM6_6MM6-MFG]  (hidden comment: APXJ160ARA271MF80J)
C19  ValueDisplayed: 47uF  [1210_270]  (hidden comment: GRM32ER61C476KE15L)
C20  Cap_F: 1µF  [0805_HV]  (hidden comment: C0805C105K3RACTU)
C21  ValueDisplayed: 22uF  [0805_HV]  (hidden comment: CL21A226KQQNNNE)
C22  ValueDisplayed: 0.1uF  [0402]  (hidden comment: GRM152B30J104KE19)
C23  ValueDisplayed: 0.01µF  [0402]  (hidden comment: C0402C103K4RACTU)
DC7  STPS30M100DJF-TR  [FP-STPS30M100DJF-TR_PowerFlat6-MFG]  (value not drawn)
J1  831-87-004-10-001101  [FP-831-87-004-10-001101_CONN_SOCKET_4-MFG]
L1  XGL6060-332MEC  [FP-XGL6060-332MEC_SMT_6MM51_6MM71-MFG]
R11  ValueDisplayed: 100k  [0402]  (hidden comment: RMCF0402FT100K)
R12  ValueDisplayed: 0.005  [KRL2012]  (hidden comment: KRL2012M-R005-F-T1)
R13  ValueDisplayed: 5.76k  [0402]  (hidden comment: CRCW04025K76FKED)
R14  ValueDisplayed: 49.9k  [0402]  (hidden comment: MCR01MZPF4992)
R15  ValueDisplayed: 71.5k  [0402]  (hidden comment: CRCW040271K5FKED)
R16  ValueDisplayed: 20.5k  [0402]  (hidden comment: CRCW040220K5FKED)
R17  ValueDisplayed: 49.9k  [0402]  (hidden comment: CRCW040249K9FKED)
R18  ValueDisplayed: 0  [0603]  (hidden comment: RC0603JR-070RL)
R19  ValueDisplayed: 49.9k  [0402]  (hidden comment: CRCW040249K9FKED)
R20  ValueDisplayed: 220k  [0402]  (hidden comment: RC0402FR-07220KL)
R21  ValueDisplayed: 30.0k  [0402]  (hidden comment: CRCW040230K0FKED)
R22  ValueDisplayed: 30.0k  [0402]  (hidden comment: CRCW040230K0FKED)
U1  LM70880RRXRQ1  [RRX0029B-MFG]
U2  TLV71333PQDBVRQ1  [DBV0005A_N]
U3  TPSM863252RDX  [RDX0007A-MFG]

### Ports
3V3 (out), 5V (in), 5V (out), 12V (in), 12VFAN (in), 12VFAN (out), UC_FAN_CLK (in), UC_FAN_PWM (in), VAUX (in), VBATAUX (in)

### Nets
12V: C9.2 C19.1 C20.1 DC7.1(A) DC7.2(A) DC7.3(A) DC7.4(A) R12.2 R19.2 U1.6(BIAS) U1.12(VOUT) U3.1(VIN) ; port 12V
SGND: C4.1 C5.1 C6.1 C7.1 C8.1 C9.1 C10.2 C11.2 C12.2 C13.2 C14.2 C15.1(CATHODE) C16.1(CATHODE) C19.2 C20.2 C21.2 C22.2 C23.2 J1.4 R15.1 R16.1 R17.1 R21.1 R22.1 U1.17(AGND) U1.23(PGND1) U1.24(PGND2) U1.25(PGND3) U1.26(PGND4) U1.30(PGND) U2.2(GND) U3.4(PGND)
VAUX: C4.2 C5.2 C6.2 C7.2 R11.2 U1.1(VIN4) U1.2(VIN5) U1.3(VIN6) U1.27(VIN1) U1.28(VIN2) U1.29(VIN3) ; port VAUX
3V3: C13.1 U2.5(OUT) ; port 3V3
5V: C14.1 C21.1 C22.1 R20.2 U2.1(IN) U2.3(EN) U3.3(VOUT) ; port 5V
12VFAN: C15.2(ANODE) C16.2(ANODE) DC7.5(K) J1.3 ; port 12VFAN
UC_FAN_CLK: J1.1 ; port UC_FAN_CLK
UC_FAN_PWM: R18.1 ; port UC_FAN_PWM
NetC3_1: C3.1 L1.1 U1.5(SW4) U1.20(SW1) U1.21(SW2) U1.22(SW3)
NetC3_2: C3.2 U1.4(CBOOT)
NetC8_2: C8.2 U1.19(VCC)
NetC10_1: C10.1 R13.2 U1.15(EXTCOMP)
NetC11_1: C11.1 R13.1
NetC12_1: C12.1 R14.1 U1.18(VDDA)
NetC23_1: C23.1 R19.1 R22.2 U3.6(EN)
NetJ1_2: J1.2 R18.2
NetL1_2: L1.2 R12.1 U1.11(ISNS+)
NetR11_1: R11.1 R16.2 U1.9(EN/UVLO)
NetR14_2: R14.2 U1.16(FB)
NetR15_2: R15.2 U1.13(CONFIG)
NetR17_2: R17.2 U1.14(RT)
NetR20_1: R20.1 R21.2 U3.7(FB)

Not connected (* = marked no-connect by the designer): U1 7(PG/SYNCOUT) 8(PFM/SYNCIN) 10(NC); U2 4(NC); U3 2(SW)* 5(PG)*

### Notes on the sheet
- 12V/12VFAN/5V/3V3
- DRSS Enabled
- 440kHz
- Compensation needs lab verification
- (near C14) 0.1Amax
- (near C13) 0.1Amax
- J2 AUX
- (near J1) DNP
- DNP

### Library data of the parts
C3 C12 = CMP-0080610-1: CAP, CERM, 0.1 µF, 25 V,+/- 10%, X7R, AEC-Q200 Grade 1, 0402; Manufacturer: TDK; TaMin_C: -55°C; Polarized: N; SizeAreaWB_mm2: 3; U/M: EA; Value: 0.1uF; TaMax_C: 125°C; SizeZ_mm: 0.6; SizeX_mm: 1; SizeY_mm: 0.5; AEC Qualified: Y; Cap_F: 100nF; AEC Category: Q200
C4-C7 = CMP-0125197-1: 100V 4.7uF X7R ±20% 1206 Multilayer Ceramic Capacitors MLCC - SMD/SMT ROHS; Manufacturer: HRE; AEC Qualified: No; Cap_F: 4.7µF; SizeZ_mm: 1.8mm; TempCo: 15%; Value: 4.7µF
C8 = CMP-0080701-1: CAP, CERM, 4.7 µF, 16 V,+/- 10%, X7R, AEC-Q200 Grade 1, 0805; Manufacturer: TDK; SizeAreaWB_mm2: 6.75; SizeArea_mm2: 2.5; AEC Qualified: Y; AEC Category: Q200; Value: 4.7uF; TaMax_C: 125°C; SizeZ_mm: 1.45; AEC Grade: 1; Polarized: N; TaMin_C: -55°C; SizeY_mm: 1.25; U/M: EA; SizeX_mm: 2; Cap_Case: 0805
C9 = CMP-0091700-1: 47µF ±10% 16V Ceramic Capacitor X5R 1210 (3225 Metric); Manufacturer: Taiyo Yuden; SizeZ_mm: 2.8mm; AEC Grade: Grade 3; TempCo: 15%; AEC Qualified: Yes
C10 = CMP-0006312-2: CAP, CERM, 47 pF, 50 V, +/- 5%, C0G/NP0, AEC-Q200 Grade 0, 0402; Manufacturer: TDK; TaMin_C: -55°C; Polarized: N; SizeAreaWB_mm2: 3; Value1: Unknown; U/M: EA; Value: 47pF; TaMax_C: 150°C; SizeZ_mm: 0.6; SizeX_mm: 1; SizeY_mm: 0.5; AEC Qualified: Y; AEC Grade: 0; AEC Category: Q200
C11 = CMP-0006323-2: CAP, CERM, 6800 pF, 50 V, +/- 10%, X7R, AEC-Q200 Grade 1, 0402; Manufacturer: TDK; TaMin_C: -55°C; ESR_ohm: 0.3916; Polarized: N; SizeAreaWB_mm2: 3; Value1: 0.391597 ohm; U/M: EA; Value: 6800pF; TaMax_C: 125°C; SizeZ_mm: 0.6; SizeX_mm: 1; SizeY_mm: 0.5; AEC Qualified: Y; Cap_F: 6.8nF; IRMS_A: 315.526mA; AEC Category: Q200
C13 C14 C22 = CMP-0006371-2: CAP, CERM, 0.1 uF, 6.3 V, +/- 10%, B, 0402; Manufacturer: MuRata; Polarized: N; CompType: Capacitor; Value: 0.1uF; U/M: EA; Cap_F: 100nF; Value1: Unknown; VDC_V: 6.3V; TaMin_C: -25°C; TaMax_C: 85°C
C15 C16 = CMP-0124190-1: 270 µF 16 V Aluminum - Polymer Capacitors Radial, Can - SMD 10mOhm 15000 Hrs @ 105°C; Manufacturer: Chemi-Con; AEC Qualified: No; Cap_F: 270µF; IRMS_A: 5.08A; SizeZ_mm: 8mm; Tolerance_%: 20%; Dissipation Factor: 12%; Esr: 10m; Leakage Current: 864uA; Life: 15000Hours; Value: 270µF
C19 = CMP-0009211-2: CAP, CERM, 47 uF, 16 V, +/- 10%, X5R, 1210; Manufacturer: MuRata; TaMin_C: -55°C; Polarized: N; SizeAreaWB_mm2: 14.7; Value1: Unknown; U/M: EA; Value: 47uF; TaMax_C: 85°C; SizeZ_mm: 2.7; SizeX_mm: 3.2; SizeY_mm: 2.5; Cap_Case: 1210; Value2: 16V; SizeArea_mm2: 8; CompType: Capacitor; Cap_F: 47µF; AEC Category: Q200
C20 = CMP-0007728-2: CAP, CERM, 1 uF, 25 V, +/- 10%, X7R, 0805; Manufacturer: Kemet; TaMin_C: -55°C; Polarized: N; SizeAreaWB_mm2: 6.75; Value1: Unknown; U/M: EA; Value: 1uF; TaMax_C: 125°C; SizeZ_mm: 1.45; SizeX_mm: 2; SizeY_mm: 1.25; Cap_Case: 0805; Value2: 25V; SizeArea_mm2: 2.5; CompType: Capacitor; AEC Category: Q200
C21 = CMP-0007989-2: CAP, CERM, 22 uF, 6.3 V, +/- 10%, X5R, 0805; Manufacturer: Samsung Electro-Mechanics; TaMin_C: -55°C; Polarized: N; SizeAreaWB_mm2: 6.75; Value1: Unknown; U/M: EA; Value: 22uF; TaMax_C: 85°C; SizeZ_mm: 1.45; SizeX_mm: 2; SizeY_mm: 1.25; Cap_Case: 0805; Value2: 6.3V; SizeArea_mm2: 2.5; CompType: Capacitor; Cap_F: 22µF; AEC Category: Q200
C23 = CMP-0078218-1: CAP, CERM, 0.01 µF, 16 V,+/- 10%, X7R, 0402; Manufacturer: Kemet; TaMin_C: -55°C; Polarized: N; Green_Lifecycle: Active; SizeAreaWB_mm2: 3; Green_REACh: Passed; U/M: EA; Value: 0.01uF; TaMax_C: 125°C; SizeZ_mm: 0.6; SizeX_mm: 1; SizeY_mm: 0.5; Value2: 16V; CompType: Capacitor; Cap_F: 10nF; AEC Category: Q200
DC7 = CMP-0032275-1: as DC2 on sheet PMP41155_Aux Power
J1 = CMP-0125223-1: Conn Socket Strip SKT 4 POS 2mm Solder ST Thru-Hole Box; Manufacturer: Preci-Dip; ContactFinish: Gold; Current_A: 3A; Row_Count: 1; Voltage_V: 150V; AEC Qualified: No; Conn Gender: Female; Conn Orientation: Vertical; Is Female: yes; SizeZ_mm: 4.2mm
L1 = CMP-0093175-1: Shielded Power Inductors 3.3uH 20% tol, 6.5mOhm 16.6A; Manufacturer: Coilcraft; Shrouded: true; AEC Grade: Grade 1; TaMin_C: -40°C; Ind_H: 3.3µH; Test Frequency: 1MHz; DCR_ohm: 6.5m; Isat: 6.6A; Material: Composite; Self Resonant Frequency: 24MHz; SizeZ_mm: 6.1mm; AEC Qualified: Yes; TaMax_C: +125°C
R11 = CMP-0026753-1: RES, 100 k, 1%, 0.063 W, AEC-Q200 Grade 0, 0402; Manufacturer: Stackpole Electronics Inc; Power_W: 63mW; TempCo: 100 ppm/C; U/M: EA; Value: 100k; EIA_Code: E96; SizeX_mm: 1; SizeY_mm: 0.5; SizeZ_mm: 0.6; Value2: 0.063W; AEC Qualified: Y; VDC_V: 50V; AEC Grade: 0; AEC Category: Q200
R12 = CMP-0015100-2: RES, 0.005, 1%, 1 W, AEC-Q200 Grade 0, 0508; Manufacturer: Susumu Co Ltd; Power_W: 1W; TempCo: 25 ppm/C; Value_Code: 5L000; U/M: EA; Value: 0.005; EIA_Code: E96; Res_ohm: 5m; AEC Qualified: Y; AEC Grade: 0; AEC Category: Q200
R13 = CMP-0026468-2: RES, 5.76 k, 1%, 0.063 W, AEC-Q200 Grade 0, 0402; Manufacturer: Vishay-Dale; Power_W: 63mW; TempCo: 100 ppm/C; Value_Code: 5k76; Value: 5.76k; EIA_Code: E96; SizeX_mm: 1; SizeY_mm: 0.5; SizeZ_mm: 0.6; Value2: 0.063W; AEC Qualified: Y; VDC_V: 50V; AEC Category: Q200; AEC Grade: 0
R14 = CMP-0026718-1: RES, 49.9 k, 1%, 0.063 W, 0402; Manufacturer: Rohm; Power_W: 63mW; TempCo: 100 ppm/C; Value_Code: 49k9; U/M: EA; Value: 49.9k; EIA_Code: E96; SizeX_mm: 1; SizeY_mm: 0.5; SizeZ_mm: 0.6; Value2: 0.063W; AEC Qualified: N; VDC_V: 50V; AEC Category: Q200
R15 = CMP-0026535-2: as RC5 on sheet PMP41155_Aux Power
R16 = CMP-0026163-2: RES, 20.5 k, 1%, 0.063 W, AEC-Q200 Grade 0, 0402; Manufacturer: Vishay-Dale; Power_W: 63mW; TempCo: 100 ppm/C; Value_Code: 20k5; Value: 20.5k; EIA_Code: E96; SizeX_mm: 1; SizeY_mm: 0.5; SizeZ_mm: 0.6; Value2: 0.063W; AEC Qualified: Y; VDC_V: 50V; AEC Category: Q200; AEC Grade: 0
R17 = CMP-0026403-2: RES, 49.9 k, 1%, 0.063 W, AEC-Q200 Grade 0, 0402; Manufacturer: Vishay-Dale; Power_W: 63mW; TempCo: 100 ppm/C; Value_Code: 49k9; Value: 49.9k; EIA_Code: E96; SizeX_mm: 1; SizeY_mm: 0.5; SizeZ_mm: 0.6; Value2: 0.063W; AEC Qualified: Y; VDC_V: 50V; AEC Category: Q200; AEC Grade: 0
R18 = CMP-0025885-5: RES, 0, 5%, 0.1 W, 0603; Manufacturer: Yageo; Power_W: 100mW; TempCo: 200 ppm/C; Value_Code: 0000; Value: 0; EIA_Code: E24; SizeX_mm: 1.6; SizeZ_mm: 1; Value2: 0.1W; SizeArea_mm2: 1.28; AEC Qualified: N; VDC_V: 75V; AEC Category: Q200; SizeY_mm: 0.8; SizeAreaWB_mm2: 4.68
R19 = CMP-0026403-2: RES, 49.9 k, 1%, 0.063 W, AEC-Q200 Grade 0, 0402; Manufacturer: Vishay-Dale; Power_W: 63mW; TempCo: 100 ppm/C; Value_Code: 49k9; Value: 49.9k; EIA_Code: E96; SizeX_mm: 1; SizeY_mm: 0.5; SizeZ_mm: 0.6; Value2: 0.063W; CompType: Resistor; AEC Qualified: Y; VDC_V: 50V; AEC Category: Q200; AEC Grade: 0
R20 = CMP-0026728-1: RES, 220 k, 1%, 0.0625 W, 0402; Manufacturer: Yageo America; Power_W: 62.5mW; TempCo: 100 ppm/C; U/M: EA; Value: 220k; SizeX_mm: 1; SizeY_mm: 0.5; SizeZ_mm: 0.6; CompType: Resistor; AEC Qualified: N; VDC_V: 50V; AEC Category: Q200
R21 R22 = CMP-0078244-2: RES, 30.0 k, 1%, 0.063 W, AEC-Q200 Grade 0, 0402; Manufacturer: Vishay-Dale; Power_W: 63mW; Green_Lifecycle: Active; TempCo: 100 ppm/C; Value_Code: 30k0; Green_REACh: Passed; Value: 30.0k; Res_ohm: 30k; SizeX_mm: 1; SizeY_mm: 0.5; SizeZ_mm: 0.6; Value2: 0.063W; CompType: Resistor; AEC Qualified: Y; VDC_V: 50V; AEC Grade: 0; AEC Category: Q200
U1 = CMP-0096026-3: 80-V, 8-A Synchronous DC/DC Buck Converter With Ultra-Low IQ, VQFN29; Manufacturer: Texas Instruments; Switching Frequency: 0.2-2.2MHz; CompType: IC; AEC Qualified: Yes; Max Supply Voltage: 80V; TaMin_C: -40°C; Min Supply Voltage: 4.5V; TaMax_C: +125°C; Output Voltage: 0.8-55V; Output Type: AdjustableProgrammable; Standoff Height: 0mm; AEC Grade: Grade 1; Number Of Outputs: 1; SizeZ_mm: 1mm; AEC Category: Q200; TJmax_C: +150°C
U2 = CMP-0073750-1: Capacitor-Free, 150-mA, LDO Regulator w/ Foldback Current Limit, DBV0005A (SOT-23-5); Alternate Manufacturer: Texas Instruments; SizeAreaWB_mm2: 14.82; U/M: EA; SizeZ_mm: 1.45; SizeX_mm: 2.8; SizeY_mm: 2.9; SizeArea_mm2: 8.12; CompType: IC
U3 = CMP-0097277-2: 3-V to 17-V Input, 3-A Synchronous Buck Module, QFN-FCMOD7; Manufacturer: Texas Instruments; Nominal Supply Current: 100-400uA; SizeZ_mm: 2.1mm; AEC Qualified: No; Output Type: AdjustableProgrammable; AEC Grade: NA; Standoff Height: 0mm; Max Supply Voltage: 17V; Min Supply Voltage: 3V; Number Of Outputs: 1; Switching Frequency: 1200/2000kHz; TJmax_C: +125°C; Max Duty Cycle: 95; Output Voltage: 0.6-10V; AEC Category: Q200; CompType: IC

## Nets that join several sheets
12V: PMP41155_Aux Power (CC35.2 UC1.1), PMP41155_Aux Power_D2D (12 pins)
SGND: PMP41155_Aux Power (68 pins), PMP41155_Aux Power_D2D (32 pins)
VAUX: PMP41155_Aux Power (23 pins), PMP41155_Aux Power_D2D (11 pins)
3V3: PMP41155_Aux Power (RC7.1 RC9.1), PMP41155_Aux Power_D2D (C13.1 U2.5)
5V: PMP41155_Aux Power (CC30.1 CC31.1 QC3.3 R2.2), PMP41155_Aux Power_D2D (7 pins)

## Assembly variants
001: all parts fitted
